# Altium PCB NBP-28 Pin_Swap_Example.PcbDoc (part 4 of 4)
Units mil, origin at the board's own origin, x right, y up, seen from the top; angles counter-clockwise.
Board outline 2716.54 x 4967.15 mil, 10 copper layers (Top Layer, Mid-Layer 1, VCC1V2, Mid-Layer 2, VCC, GND, MidLayer4, VCCINT, Mid-Layer 3, Bottom Layer), stack 81 mil thick; 254 components, 445 nets, 1667 pads, 770 vias.
Unrouted connection lines stored in the file: 611.
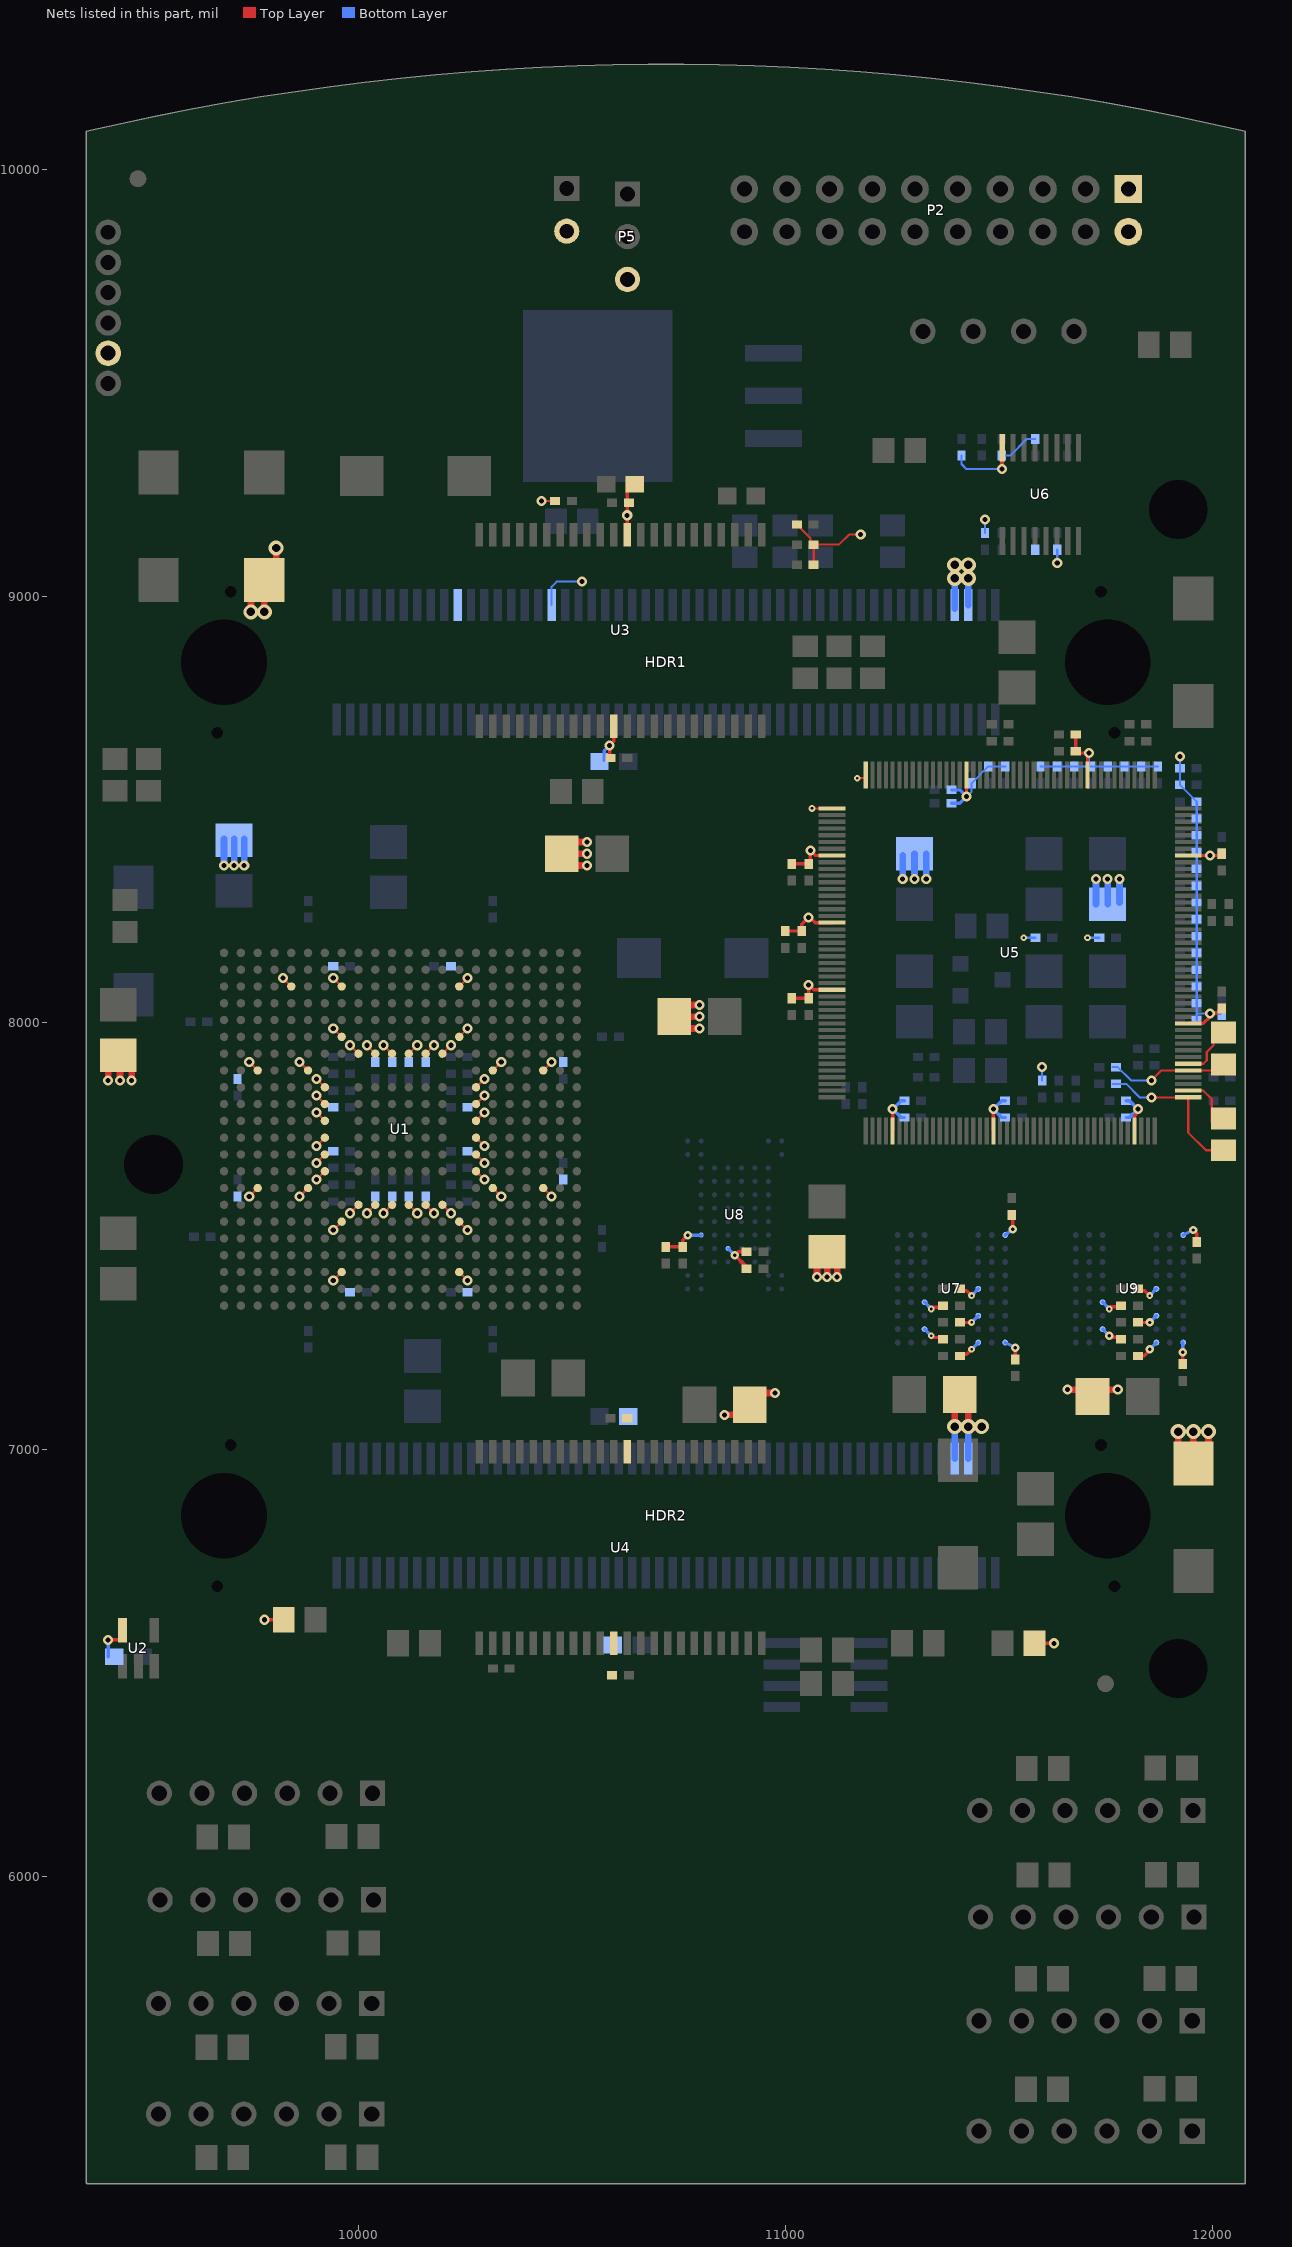
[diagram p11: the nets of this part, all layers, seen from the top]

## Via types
v1: diameter 23.62, hole 11.81, Top Layer to Bottom Layer, 495 vias
v2: diameter 78.74, hole 47.24, Top Layer to Bottom Layer, 101 vias
v3: diameter 15.75, hole 5.91, Top Layer to Bottom Layer, 92 vias
v4: diameter 35.43, hole 19.68, Top Layer to Bottom Layer, 59 vias
v5: diameter 19.68, hole 7.87, Top Layer to Bottom Layer, 23 vias

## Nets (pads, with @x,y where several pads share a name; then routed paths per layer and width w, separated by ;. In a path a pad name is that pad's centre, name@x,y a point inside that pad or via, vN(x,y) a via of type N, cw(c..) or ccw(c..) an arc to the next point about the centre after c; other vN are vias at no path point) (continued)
VCC3V3: C1.2 C12.1 C13.1 C14.1 C15.1 C30.1 C31.1 C32.1 C33.1 C34.1 C35.1 C36.1 C37.1 C38.1 C39.1 C40.1 C41.1 C42.1 C43.1 C44.1 C45.1 C46.1 C47.1 C48.1 C49.1 C50.1 C51.1 C52.1 C53.1 C54.1 C55.1 C56.1 C57.1 C58.1 C62.1 C66.1 C67.1 C68.1 C69.1 C70.1 C71.1 C72.1 C73.1 C74.1 C75.1 C76.1 C77.1 C78.1 C79.1 C80.1 C81.1 C82.1 C83.1 C84.1 C85.1 C86.1 C87.1 C102.1 C103.1 C104.1 C105.1 C106.1 C107.1 C108.1 C109.1 C110.1 C111.1 C112.1 C113.1 C114.1 C115.1 C116.1 C117.1 C118.1 C119.1 C120.1 C121.1 C122.1 C126.1 C127.1 HDR1.34 HDR1.94 HDR1.96 HDR2.94 HDR2.96 P1.2 P2.1 P2.2 P5.3 R1.1 R5.1 R15.2 R16.2 R17.2 R18.2 R20.2 R21.2 R22.2 R23.2 R24.2 R25.2 R26.2 R27.2 R28.2 R29.2 R30.2 R31.2 R32.2 R33.2 R34.2 R35.2 R39.2 R40.2 R41.2 R42.2 R43.2 R45.2 R48.2 R49.2 R50.2 R51.2 R52.2 R53.2 R54.2 R55.2 R56.2 R57.2 R61.1 R62.1 R67.1 TP1.1 U1.C8 U1.C15 U1.F8 U1.F15 U1.G9 U1.G10 U1.G11 U1.G12 U1.G13 U1.G14 U1.H3 U1.H6 U1.H17 U1.H20 U1.J7 U1.J16 U1.K7 U1.K16 U1.L7 U1.L16 U1.M7 U1.M16 U1.N7 U1.N16 U1.P7 U1.P16 U1.R3 U1.R6 U1.R17 U1.R20 U1.T9 U1.T10 U1.T11 U1.T12 U1.T13 U1.T14 U1.U8 U1.U15 U1.Y8 U1.Y15 U2.5 U3.11 U3.33 U4.11 U4.33 U5.1 U5.8 U5.18 U5.28 U5.49 U5.64 U5.85 U5.100 U5.125 U5.143 U5.161 U5.176 U6.16 U7.A7 U7.A9 U7.B3 U7.C7 U7.D3 U7.E7 U7.J9 U8.H7 U8.J5 U9.A7 U9.A9 U9.B3 U9.C7 U9.D3 U9.E7 U9.J9 | length 8194.9
  Top Layer w5: v1(9743.57,7593.48) U1.R3@9763.26,7613.17 ; v1(9743.57,7908.45) U1.H3@9763.26,7888.76 ; v1(9861.68,7593.48) U1.R6@9881.37,7613.17 ; v1(9861.68,7908.45) U1.H6@9881.37,7888.76 ; v1(9901.05,7632.85) U1.P7@9920.74,7652.54 ; v1(9901.05,7672.22) U1.N7@9920.74,7691.91 ; v1(9901.05,7711.59) U1.M7@9920.74,7731.28 ; v1(9901.05,7790.34) U1.L7@9920.74,7770.65 ; v1(9901.05,7829.71) U1.K7@9920.74,7810.02 ; v1(9901.05,7869.08) U1.J7@9920.74,7849.39 ; v1(9940.42,7396.63) U1.Y8@9960.11,7416.32 ; v1(9940.42,7514.74) U1.U8@9960.11,7534.43 ; v1(9940.42,7987.19) U1.F8@9960.11,7967.5 ; v1(9940.42,8105.3) U1.C8@9960.11,8085.61 ; v1(9979.79,7554.11) U1.T9@9999.48,7573.8 ; v1(9979.79,7947.82) U1.G9@9999.48,7928.13 ; v1(10019.16,7554.11) U1.T10@10038.85,7573.8 ; v1(10019.16,7947.82) U1.G10@10038.85,7928.13 ; v1(10058.53,7554.11) U1.T11@10078.22,7573.8 ; v1(10058.53,7947.82) U1.G11@10078.22,7928.13 ; U1.T12@10117.59,7573.8 v1(10137.27,7554.11) ; U1.G12@10117.59,7928.13 v1(10137.27,7947.82) ; U1.T13@10156.96,7573.8 v1(10176.64,7554.11) ; U1.G13@10156.96,7928.13 v1(10176.64,7947.82) ; U1.T14@10196.33,7573.8 v1(10216.01,7554.11) ; U1.G14@10196.33,7928.13 v1(10216.01,7947.82) ; U1.Y15@10235.7,7416.32 v1(10255.38,7396.63) ; U1.U15@10235.7,7534.43 v1(10255.38,7514.74) ; U1.F15@10235.7,7967.5 v1(10255.38,7987.19) ; U1.C15@10235.7,8085.61 v1(10255.38,8105.3) ; U1.P16@10275.07,7652.54 v1(10294.75,7632.85) ; U1.N16@10275.07,7691.91 v1(10294.75,7672.22) ; U1.M16@10275.07,7731.28 v1(10294.75,7711.59) ; U1.L16@10275.07,7770.65 v1(10294.75,7790.34) ; U1.K16@10275.07,7810.02 v1(10294.75,7829.71) ; U1.J16@10275.07,7849.39 v1(10294.75,7869.08) ; U1.R17@10314.44,7613.17 v1(10334.12,7593.48) ; U1.H17@10314.44,7888.76 v1(10334.12,7908.45) ; v1(10428.61,9223.41) R17.2@10460.11,9223.41 ; U1.R20@10432.55,7613.17 v1(10452.23,7593.48) ; U1.H20@10432.55,7888.76 v1(10452.23,7908.45) ; R24.2@11027.04,9168.29 11058.53,9136.79 R15.2@11058.53,9121.04 ; v3(11062.47,8502.93) U5.1@11109.71,8502.93 ; R18.2@11066.41,9073.8 R15.2@11066.41,9121.04 11125.46,9121.04 11149.08,9144.67 v1(11176.64,9144.67) ; v3(11168.77,8573.8) U5.176@11188.45,8573.8
  Top Layer w7.87: v1(9412.86,6554.11) U2.5@9452.23,6554.11 ; v1(9779,6601.36) R16.2@9824.28,6601.36 ; C53.1@10590.03,8621.04 10588.06,8623.01 v1(10588.06,8650.57) 10597.9,8660.41 U3.11@10597.9,8695.85 ; U3.33@10629.4,9139.74 U3.33@10629.4,9144.67 v1(10629.4,9189.94) C51.1@10629.4,9274.59 ; C105.1@10719.95,7475.37 C104.1@10759.32,7475.37 10759.32,7491.12 v5(10771.13,7502.93) ; C103.1@10908.93,7424.19 10908.93,7428.13 v5(10881.37,7455.69) 10889.24,7463.56 C106.1@10908.93,7463.56 ; C71.1@10999.48,8215.53 C81.1@11038.85,8215.53 11038.85,8231.28 v1(11054.59,8247.03) 11058.53,8247.03 11070.34,8235.22 U5.18@11109.71,8235.22 ; C70.1@11015.22,8058.05 C80.1@11054.59,8058.05 v1(11054.59,8089.55) 11066.41,8077.74 U5.28@11109.71,8077.74 ; C68.1@11015.22,8373.01 C78.1@11054.59,8373.01 ; C78.1@11058.53,8376.95 v1(11058.53,8404.51) 11070.34,8392.7 U5.8@11109.71,8392.7 ; U5.49@11251.45,7747.03 v1(11251.45,7798.21) ; v3(11342,7266.71) 11345.93,7262.78 C119.1@11373.49,7262.78 ; v3(11342,7329.7) 11345.93,7333.64 C121.1@11365.62,7333.64 ; C120.1@11404.99,7223.41 11424.67,7223.41 v3(11436.48,7235.22) ; C109.1@11404.99,7373.01 11424.67,7373.01 v3(11436.48,7361.2) ; C118.1@11408.93,7298.21 v3(11436.48,7298.21) ; v1(11424.67,8530.49) U5.161@11424.67,8581.67 ; U5.64@11487.67,7747.03 v1(11487.67,7798.21) ; v1(11507.35,9298.21) U6.16@11507.35,9347.42 ; v5(11532.94,7516.71) C122.1@11532.94,7548.21 ; C108.1@11538.85,7215.53 v5(11538.85,7239.15) ; R5.1@11584.12,6546.24 v1(11629.4,6546.24) ; C86.1@11680.58,8636.79 C76.1@11680.58,8676.16 ; C86.1@11684.52,8632.85 v1(11712.08,8632.85) ; U5.143@11708.14,8581.67 v1@11708.14,8628.92 ; v3@11758.32,7330.7 11762.26,7334.64 C116.1@11781.95,7334.64 ; v5@11758.33,7267.71 11762.26,7263.78 C115.1@11789.82,7263.78 ; U5.85@11818.37,7747.03 11818.37,7782.46 11826.25,7790.33 v1(11826.25,7798.21) ; C117.1@11821.32,7220.47 11841,7220.47 v5@11852.82,7232.28 ; C107.1@11822.31,7373.01 11842,7373.01 v3(11853.81,7361.2) ; C112.1@11826.25,7298.21 v5(11853.81,7298.21) ; C114.1@11931.56,7200.78 v5(11931.56,7228.34) ; U5.100@11944.36,7999 11979.79,7999 11995.54,8014.74 v1(11995.54,8022.62) 12011.29,8022.62 C84.1@12023.1,8034.43 ; U5.125@11944.36,8392.7 v1(11995.54,8392.7) C75.1@12019.16,8392.7 ; v5(11956.17,7514.74) 11964.04,7506.87 C113.1@11964.04,7487.18
  Top Layer w15.75: C32.1@9404.99,7928.13 9412.86,7924.19 v1(9412.86,7865.14) ; C32.1@9436.48,7928.13 9440.42,7924.19 v1(9440.42,7865.14) ; v1(9467.98,7865.14) C32.1@9467.98,7928.13 ; v4(9747.51,8963.56) C127.1@9747.51,9026.55 ; v4(9779,8963.56) C127.1@9779,9022.62 ; C127.1@9806.56,9050.18 v4(9806.56,9113.17) ; C49.1@10471.92,8369.07 v1(10534.91,8369.07) ; C49.1@10471.92,8424.19 v1(10534.91,8424.19) ; C49.1@10475.85,8396.63 v1(10534.91,8396.63) ; C31.1@10735.7,7987.18 v1(10798.69,7987.18) ; C31.1@10735.7,8042.3 v1(10798.69,8042.3) ; C31.1@10739.63,8014.74 v1(10798.69,8014.74) ; v1(10857.74,7081.67) C50.1@10908.93,7081.67 ; C50.1@10912.86,7132.85 v1(10975.85,7132.85) ; v1(11074.28,7404.51) C102.1@11074.28,7447.81 ; v1(11097.9,7404.51) C102.1@11097.9,7455.69 ; v1(11121.52,7404.51) C102.1@11121.52,7451.75 ; v4(11397.11,7054.11) C110.1@11397.11,7113.17 ; C110.1@11408.93,7128.92 11428.61,7109.23 v4(11428.61,7054.11) ; v1(11660.89,7140.73) v1(11779,7140.73) ; C126.1@11920.74,6999 v4(11920.74,7042.3) ; C126.1@11956.17,6967.5 v4(11956.17,7042.3) ; C126.1@11991.6,6983.25 v4(11991.6,7042.3)
  Bottom Layer w5: HDR1.34@10452.23,8979.31 10452.23,9022.62 10464.04,9034.43 v1(10523.1,9034.43) ; R67.1@11412.86,9329.7 11412.86,9310.02 11424.67,9298.21 v1(11507.35,9298.21) ; v1(11424.67,8530.49) 11436.48,8542.3 R56.2@11436.48,8561.99 R55.2@11475.85,8601.36 R54.2@11515.22,8601.36 ; R57.2@11467.98,9148.6 v1(11467.98,9180.1) ; C62.1@11507.35,9329.7 11527.04,9329.7 11566.41,9369.07 R62.1@11586.09,9369.07 ; v3(11558.53,8199.78) R29.2@11586.09,8199.78 ; R52.2@11597.9,8601.36 R51.2@11712.08,8601.36 ; R20.2@11601.84,7865.14 v1(11601.84,7896.63) ; v1(11637.27,9077.74) R61.1@11637.27,9109.23 ; v3(11708.14,8199.78) R30.2@11735.7,8199.78 ; v1(11712.08,8632.85) R51.2@11712.08,8601.36 ; R41.2@11873.49,8601.36 R42.2@11834.12,8601.36 R51.2@11712.08,8601.36 ; v1(11924.67,8624.98) R49.2@11924.67,8597.42 R40.2@11924.67,8558.05 R48.2@11964.04,8518.68 R39.2@11964.04,8479.31 R28.2@11964.04,8321.83 R35.2@11964.04,8203.72 R21.2@11964.04,8085.61 11964.04,8022.62 ; R23.2@11964.04,8006.87 11964.04,8022.62 ; R26.2@11967.98,8392.7 v1(11995.54,8392.7) ; v1(11995.54,8022.62) 11964.04,8022.62
  Bottom Layer w7.87: C1.2@9412.86,6514.74 v1(9412.86,6554.11) ; C52.1@10575.26,8615.14 10575.26,8637.78 v1(10588.06,8650.57) ; v5(10771.13,7502.93) U8.H7@10802.63,7502.93 ; U8.J5@10865.62,7471.44 v5(10881.37,7455.69) ; C79.1@11279,7778.52 11271.13,7778.52 v1(11251.45,7798.21) 11271.13,7817.89 C69.1@11279,7817.89 ; U7.B3@11326.25,7282.46 v3(11342,7266.71) ; U7.D3@11326.25,7345.45 v3(11342,7329.7) ; C87.1@11389.24,8514.74 11408.93,8514.74 v1(11424.67,8530.49) 11408.93,8546.24 C77.1@11389.24,8546.24 ; v3(11436.48,7235.22) U7.A7@11452.23,7250.96 ; v3(11436.48,7298.21) U7.C7@11452.23,7313.96 ; v3(11436.48,7361.2) U7.E7@11452.23,7376.95 ; v1(11507.35,9298.21) C62.1@11507.35,9329.7 ; U7.A9@11515.22,7250.96 v5(11538.85,7239.15) ; U7.J9@11515.22,7502.93 v5(11532.94,7516.71) ; C83.1@11515.22,7778.52 11507.35,7778.52 v1(11487.67,7798.21) 11507.35,7817.89 C73.1@11515.22,7817.89 ; U9.B3@11743.57,7282.46 v5(11759.32,7266.71) ; U9.D3@11743.57,7345.45 v3(11759.32,7329.7) ; C82.1@11798.69,7778.52 11806.56,7778.52 v1(11826.25,7798.21) 11806.56,7817.89 C72.1@11798.69,7817.89 ; v5(11853.81,7235.22) U9.A7@11869.56,7250.96 ; v5(11853.81,7298.21) U9.C7@11869.56,7313.96 ; v3(11853.81,7361.2) U9.E7@11869.56,7376.95 ; v5(11931.56,7228.34) U9.A9@11931.56,7251.96 ; U9.J9@11932.55,7502.93 v5(11956.17,7514.74) ; v1(11995.54,8022.62) C74.1@12019.16,8022.62 ; v1(11995.54,8392.7) C85.1@12019.16,8392.7
  Bottom Layer w15.75: v1(9684.52,8369.07) C30.1@9684.52,8432.07 ; v1(9708.14,8369.07) C30.1@9708.14,8428.13 C30.1@9708.14,8432.07 ; v1(9731.76,8369.07) C30.1@9731.76,8432.07 ; v1(11275.07,8337.58) C67.1@11275.07,8392.7 ; v1(11302.63,8337.58) C67.1@11302.63,8396.63 ; v1(11330.19,8337.58) C67.1@11330.19,8396.63 ; HDR2.94@11397.12,6979.31 v4(11397.11,7054.11) v4(11428.61,7054.11) ; HDR1.94@11397.11,8971.44 HDR1.94@11397.11,8979.31 v4(11397.11,9042.3) ; HDR2.96@11428.61,6979.31 v4(11428.61,7054.11) ; HDR1.96@11428.61,8979.31 v4(11428.61,9042.3) ; v4(11460.11,7054.11) v4(11428.61,7054.11) ; C66.1@11727.82,8278.52 v1(11727.82,8337.58) ; C66.1@11755.38,8278.52 v1(11755.38,8337.58) ; C66.1@11782.94,8282.46 v1(11782.94,8337.58) ; v4(11397.11,9042.3) v4(11428.61,9042.3) ; v4(11397.11,9042.3) v4(11397.11,9073.8) v4(11428.61,9073.8) v4(11428.61,9042.3)
VDRIVE: HDR1.20 U1.C5 | length 27.8
  Top Layer w5: v1(9822.31,8105.3) U1.C5@9842,8085.61
XTALIN: C59.2 R38.1 U5.93 | length 278.7
  Top Layer w5: v1(11857.74,7865.14) 11881.37,7888.76 U5.93@11944.36,7888.76 R38.1@12023.1,7888.76
  Bottom Layer w5: C59.2@11767.19,7896.63 C59.2@11775.07,7896.63 11779,7896.63 11810.5,7865.14 v1(11857.74,7865.14)
XTALIN_32K: C60.2 R47.1 U5.89 | length 372.7
  Top Layer w5: v1(11857.74,7825.77) U5.89@11944.36,7825.77 11944.36,7743.09 11985.7,7701.75 R47.1@12027.04,7701.75
  Bottom Layer w5: C60.2@11767.19,7857.26 C60.2@11775.07,7857.26 11798.69,7857.26 11830.19,7825.77 v1(11857.74,7825.77)
XTALOUT: R38.2 U5.94 | length 108.2
  Top Layer w5: U5.94@11944.36,7904.51 11979.79,7904.51 11987.67,7912.38 11987.67,7932.07 12003.41,7947.81 R38.2@12003.41,7967.5
XTALOUT_32K: R47.2 U5.90 | length 118.4
  Top Layer w5: U5.90@11944.36,7841.52 11979.79,7841.52 11999.48,7821.83 R47.2@11999.48,7766.71
pads on no net: D1.2 HDR1.91 HDR1.MH1 HDR1.MH2 HDR1.MH3 HDR1.MH4 HDR1.MH5 HDR1.MH6 HDR2.MH1 HDR2.MH2 HDR2.MH3 HDR2.MH4 HDR2.MH5 HDR2.MH6 P3_ch1.3 P3_ch1.6 P3_ch2.3 P3_ch2.6 P3_ch3.3 P3_ch3.6 P3_ch4.3 P3_ch4.6 P4_ch1.3 P4_ch1.6 P4_ch2.3 P4_ch2.6 P4_ch3.3 P4_ch3.6 P4_ch4.3 P4_ch4.6 U2.1 U5.145 U5.157 U5.162 U7.E2 U8.A1 U8.A2 U8.A7 U8.A8 U8.B1 U8.B7 U8.B8 U8.L1 U8.L2 U8.L7 U8.L8 U8.M1 U8.M2 U8.M7 U8.M8 U9.E2 U10.5 U10.8

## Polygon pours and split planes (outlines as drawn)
VCC1V2 on VCC1V2 (split plane): 10788.26,10226.6 10856.59,10225.42 10924.91,10223.45 10993.19,10220.69 11061.44,10217.14 11129.64,10212.8 11197.79,10207.67 11265.88,10201.76 11333.89,10195.06 11401.82,10187.58 11469.66,10179.31 11537.4,10170.26 11605.02,10160.43 11672.54,10149.81 11739.92,10138.42 11807.17,10126.25 11874.27,10113.31 11941.22,10099.59 12008.01,10085.09 12058.12,10073.61 12058.12,5299.8 9381.78,5299.8 9381.78,10073.63 9431.84,10085.09 9498.62,10099.59 9565.57,10113.31 9632.68,10126.25 9699.92,10138.42 9767.31,10149.81 9834.82,10160.43 9902.45,10170.26 9970.19,10179.31 10038.03,10187.58 10105.96,10195.06 10173.97,10201.76 10242.06,10207.67 10310.2,10212.8 10378.41,10217.14 10446.66,10220.69 10514.94,10223.45 10583.25,10225.42 10651.58,10226.6 10719.92,10227
VCC1V8 on VCC1V2 (split plane): 12044.9,8692.89 12044.9,7865 12044.9,6557.11 12039.13,6551.34 11375.87,6551.34 11305.1,6622.11 11305.1,7630 11304.71,7631.95 11303.6,7633.6 11100.1,7837.11 11100.1,8442.89 11353.6,8696.4 11353.61,8696.4 11382.11,8724.9 12012.89,8724.9
VCC3V3 on VCC (split plane): 10788.26,10226.6 10856.59,10225.42 10924.91,10223.45 10993.19,10220.69 11061.44,10217.14 11129.64,10212.8 11197.79,10207.67 11265.88,10201.76 11333.89,10195.06 11401.82,10187.58 11469.66,10179.31 11537.4,10170.26 11605.02,10160.43 11672.54,10149.81 11739.92,10138.42 11807.17,10126.25 11874.27,10113.31 11941.22,10099.59 12008.01,10085.09 12058.12,10073.61 12058.12,5299.8 9381.78,5299.8 9381.78,10073.63 9431.84,10085.09 9498.62,10099.59 9565.57,10113.31 9632.68,10126.25 9699.92,10138.42 9767.31,10149.81 9834.82,10160.43 9902.45,10170.26 9970.19,10179.31 10038.03,10187.58 10105.96,10195.06 10173.97,10201.76 10242.06,10207.67 10310.2,10212.8 10378.41,10217.14 10446.66,10220.69 10514.94,10223.45 10583.25,10225.42 10651.58,10226.6 10719.92,10227
GND on GND (split plane): 10788.26,10226.6 10856.59,10225.42 10924.91,10223.45 10993.19,10220.69 11061.44,10217.14 11129.64,10212.8 11197.79,10207.67 11265.88,10201.76 11333.89,10195.06 11401.82,10187.58 11469.66,10179.31 11537.4,10170.26 11605.02,10160.43 11672.54,10149.81 11739.92,10138.42 11807.17,10126.25 11874.27,10113.31 11941.22,10099.59 12008.01,10085.09 12058.12,10073.61 12058.12,5299.8 9381.78,5299.8 9381.78,10073.63 9431.84,10085.09 9498.62,10099.59 9565.57,10113.31 9632.68,10126.25 9699.92,10138.42 9767.31,10149.81 9834.82,10160.43 9902.45,10170.26 9970.19,10179.31 10038.03,10187.58 10105.96,10195.06 10173.97,10201.76 10242.06,10207.67 10310.2,10212.8 10378.41,10217.14 10446.66,10220.69 10514.94,10223.45 10583.25,10225.42 10651.58,10226.6 10719.92,10227
VCC2V5 on VCCINT (split plane): 10788.26,10226.6 10856.59,10225.42 10924.91,10223.45 10993.19,10220.69 11061.44,10217.14 11129.64,10212.8 11197.79,10207.67 11265.88,10201.76 11333.89,10195.06 11401.82,10187.58 11469.66,10179.31 11537.4,10170.26 11605.02,10160.43 11672.54,10149.81 11739.92,10138.42 11807.17,10126.25 11874.27,10113.31 11941.22,10099.59 12008.01,10085.09 12058.12,10073.61 12058.12,9459.09 12053.6,9463.6 12051.95,9464.71 12050,9465.1 11085,9465.1 11083.05,9464.71 11081.4,9463.6 10946.4,9328.6 10945.29,9326.95 10944.9,9325 10944.9,6615 10945.29,6613.05 10946.4,6611.4 11031.4,6526.4 11033.05,6525.29 11035,6524.9 12050,6524.9 12051.95,6525.29 12053.6,6526.4 12058.12,6530.91 12058.12,5299.8 9381.78,5299.8 9381.78,10073.63 9431.84,10085.09 9498.62,10099.59 9565.57,10113.31 9632.68,10126.25 9699.92,10138.42 9767.31,10149.81 9834.82,10160.43 9902.45,10170.26 9970.19,10179.31 10038.03,10187.58 10105.96,10195.06 10173.97,10201.76 10242.06,10207.67 10310.2,10212.8 10378.41,10217.14 10446.66,10220.69 10514.94,10223.45 10583.25,10225.42 10651.58,10226.6 10719.92,10227
+5V on VCCINT (split plane): 12054.9,9447.89 12054.9,6542.11 12047.89,6535.1 11037.11,6535.1 10955.1,6617.11 10955.1,9322.89 11087.11,9454.9 12047.89,9454.9

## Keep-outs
Top Layer:
  circle w10: c11750.4,6451.11 r98.43
  circle w10: c9482.69,9978.67 r98.43
Bottom Layer:
  circle w10: c11750.4,6451.11 r98.43
  circle w10: c9482.69,9978.67 r98.43
  rectangle: 11471.92,9707.66 11668.77,9802.14
Keep-Out Layer:
  the board outline again, w31.5

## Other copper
Bottom Layer:
  region: 11562.47,7439.94 11617.59,7439.94
VCCINT (plane layer: these items are gaps in the copper):
  lines w10: 10950,6615 11035,6530 11160,6530 12050,6530 12060,6540 12060,9450 12050,9460 11085,9460 10950,9325 10950,6615
VCC1V2 (plane layer: these items are gaps in the copper):
  lines w10: 11095,7835 11300,7630 11300,6620 11373.76,6546.24 11481.24,6546.24 12041.24,6546.24 12050,6555 12050,7865 12050,8695 12015,8730 11750,8730 11380,8730 11350,8700 11095,8445 11095,7835

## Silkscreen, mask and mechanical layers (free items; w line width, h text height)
Top Overlay:
  circle w5: c11920.74,9203.72 r98.43
  circle w5: c9519.16,7668.29 r98.43
  circle w5: c11920.74,6487.18 r62.99
  circle w5: c9519.16,7668.29 r62.99
  circle w5: c9519.16,7668.29 r108.27
  circle w5: c11920.74,9203.72 r62.99
  circle w5: c11920.74,9203.72 r108.27
  circle w10: c11605.78,7569.86 r106.3
  circle w10: c11578.22,7231.28 r106.3
  circle w10: c10452.23,9282.46 r98.43
  lines w3.15: 11086.09,9589.55 11290.82,9589.55 11322.31,9621.04 ; 11093.97,9660.41 11401.05,9660.41 11440.42,9621.04 ; 11440.42,9660.41 11519.16,9660.41 11558.53,9621.04 ; 11676.64,9621.04 11716.01,9660.41 11822.31,9660.41 ; 12034.91,8010.81 12050.66,8026.55 12050.66,8199.78
  lines w5: 9361.68,6378.92 9401.05,6378.92 9404.68,6378.23 9408.01,6376.03 9410.2,6372.7 9410.89,6369.08 9410.89,6329.7 ; 9361.68,6388.76 9420.74,6388.76 9420.74,6329.7 ; 9361.68,7820.85 9440.42,7820.85 9444.05,7821.54 9447.38,7823.73 9449.57,7827.06 9450.26,7830.69 9450.26,7860.22 9449.57,7863.84 9447.38,7867.18 9444.05,7869.37 9440.42,7870.06 9361.68,7870.06 ; 9361.68,9302.15 9420.74,9302.15 9420.74,9357.26 ; 9361.68,9321.83 9401.05,9321.83 9404.68,9322.52 9408.01,9324.71 9410.2,9328.05 9410.89,9331.67 9410.89,9355.3 ; 9361.73,9345.45 cw(c10719.97,3565.9) 12078.22,9345.45 ; 9361.73,9424.19 cw(c10719.97,3644.64) 12078.22,9424.19 ; 9362.02,7189.51 9452.57,7189.51 9452.57,7264.31 9362.05,7264.31 ; 9362.02,8421.79 9452.57,8421.79 9452.57,8496.59 9362.05,8496.59 ; 9479.79,7668.29 9519.16,7668.29 ; 9519.16,7628.92 9519.16,7668.29 ; 9519.16,7707.66 9519.16,7668.29 ; 9558.53,7668.29 9519.16,7668.29 ; 9979.79,9455.69 9979.79,9404.51 10030.97,9404.51 10030.97,9459.63 ; 10085.11,9466.52 10085.11,9410.81 10085.8,9407.18 10087.99,9403.85 10091.33,9401.66 10094.95,9400.96 10124.48,9400.96 10128.1,9401.66 10131.44,9403.85 10133.63,9407.18 10134.32,9410.81 10134.32,9472.42 ; 10090.03,6546.24 10129.4,6546.24 ; 10129.4,6506.87 10129.4,6546.24 ; 10129.4,6585.61 10129.4,6546.24 ; 10168.77,6546.24 10129.4,6546.24 ; 11271.13,6546.24 11310.5,6546.24 ; 11305.58,9472.42 11305.58,9410.81 11306.27,9407.18 11308.46,9403.85 11311.8,9401.66 11315.42,9400.96 11344.95,9400.96 11348.57,9401.66 11351.91,9403.85 11354.1,9407.18 11354.79,9410.81 11354.79,9466.52 ; 11310.5,6506.87 11310.5,6546.24 ; 11310.5,6585.61 11310.5,6546.24 ; 11318.37,9471.44 11318.37,9428.13 11369.55,9428.13 11369.56,9467.5 ; 11349.87,6546.24 11310.5,6546.24 ; 11819,6524.21 cw(c11920.74,6487.18) 11844.18,6410.63 ; 11828.25,6520.85 cw(c11920.74,6487.19) 11845.34,6423.92 ; 11881.37,6487.18 11920.74,6487.18 ; 11881.37,9203.72 11920.74,9203.72 ; 11920.74,6447.81 11920.74,6487.18 ; 11920.74,6526.55 11920.74,6487.18 ; 11920.74,9164.35 11920.74,9203.72 ; 11920.74,9243.09 11920.74,9203.72 ; 11960.11,6487.18 11920.74,6487.18 ; 11960.11,9203.72 11920.74,9203.72 ; 12019.16,6329.7 12019.16,6388.76 12078.22,6388.76 ; 12019.16,9357.26 12019.16,9302.14 12078.22,9302.14 ; 12029,6329.7 12029,6369.08 12029.7,6372.7 12031.89,6376.03 12035.22,6378.23 12038.85,6378.92 12078.22,6378.92 ; 12029,9355.3 12029,9331.67 12029.7,9328.05 12031.89,9324.71 12035.22,9322.52 12038.85,9321.83 12078.22,9321.83 ; 12078.19,7191.91 11987.66,7191.91 11987.66,7266.71 12078.22,7266.71 ; 12078.22,7820.85 11999.48,7820.85 11995.85,7821.54 11992.52,7823.73 11990.33,7827.06 11989.63,7830.69 11989.63,7860.22 11990.33,7863.84 11992.52,7867.18 11995.85,7869.37 11999.48,7870.06 12078.22,7870.06 ; 12078.53,8424.19 11988.01,8424.19 11988.01,8499 12078.56,8499 ; 10090.03,6506.87 cw(c10090.03,6546.24) 10090.03,6585.61 10168.77,6585.61 cw(c10168.77,6546.24) 10168.77,6506.87 10090.03,6506.87 ; 11271.13,6506.87 cw(c11271.13,6546.24) 11271.13,6585.61 11349.87,6585.61 cw(c11349.87,6546.24) 11349.87,6506.87 11271.13,6506.87
  text "LH79520 EXT DEBUG" at 11082.15,10109.23 h31.5
  text "OPEN: INTEGRATED" at 10629.4,9648.6 h31.5 r90
  text "CLOSED: EXTERNAL" at 10672.7,9648.6 h31.5 r90
  text "LH79520 DEBUG SELECT" at 10582.15,9593.48 h31.5 r90
  text "EXT DEBUG" at 11771.13,9499 h31.5
  text "ALL" at 10412.86,9310.02 h31.5
  text "4k7" at 10408.93,9262.78 h31.5
  text "ALL" at 11566.41,7585.61 h31.5
  text "100nF" at 11558.53,7538.37 h31.5
  text "ALL" at 11554.59,7243.09 h31.5
  text "10nF" at 11562.47,7195.85 h31.5
  text "LOADED" at 10042.78,6396.63 h31.5
  text "POWER" at 11251.45,6396.63 h31.5
  text "Altium Advanced Training: '.Pcb_File_Name_No_Path'" at 9380,5166.66 h50
Bottom Overlay:
  drawing of 888 lines, arcs and shapes, not listed
  text "NBP#28" at 11738.59,10045.6 h31.5
  text "REV 1.00" at 11407.89,10041.66 h31.5
  text "1" at 9911.68,8629.7 h31.5
  text "1" at 9903.95,6675.52 h31.5
Mechanical 1:
  lines w9.84: 9361.67,5229.55 9361.7,10089.55 cw(c10719.95,4310) 12078.22,10089.54 12078.22,5229.55 ; 9361.68,5229.7 12078.22,5229.7
  text "PCB boundary coincides with centre-line of tracks and arc" at 9356.76,4813.24 h31.5
Mechanical 2:
  text ".Printout_Name" at 9356.76,5049.46 h31.5
Mechanical 3:
  text ".Printout_Name" at 9356.76,4891.98 h31.5
Mechanical 11:
  drawing of 689 lines, arcs and shapes, not listed
  text "NBP28 Rev1.00" at 20080.76,14835.7 h50
  text "DESIGN INFORMATION" at 17875.76,14830.7 h60
  text "BOARD NAME:" at 19355.76,14830.7 h60
  text "BOARD TECHNOLOGY" at 17875.76,14730.7 h60
  text "BOARD SIZE (REFER ALSO PROFILING INFORMATION)" at 19775.76,14730.7 h50
  text "5.000" at 17959.26,14644.52 h60
  text "69.00mm" at 19882.84,14641.18 h60
  text "12.000" at 18495.39,14638.57 h60
  text "81.00mm" at 20788.36,14637.24 h60
  text "5.000" at 19047.77,14632.71 h60
  text "X" at 20510.76,14610.7 h70
  text "(MIN. TRACK/   PADS  /   CLEARANCE     IN 0.001'')" at 17815.76,14530.7 h50
  text "MINIMUM ANNULAR RING 0.125MM (0.005'') EXTERNAL PER IPC-2221 CLASS 3 LEVEL C AND IS THE" at 17875.76,14430.7 h50
  text "MANUFACTURING REGISTRATION ALLOWANCE" at 17875.76,14340.7 h50
  text "LAND SIZE CALCULATION MINIMUM - NOMINAL HOLE SIZE + 0.508MM (0.020'')" at 17875.76,14230.7 h50
  text "CIRCUIT TYPE:" at 17875.76,14050.7 h60
  text "SS" at 18775.76,14050.7 h50
  text "DS" at 19475.76,14050.7 h50
  text "X" at 20050.76,14050.7 h60
  text "PTH" at 20175.76,14050.7 h50
  text "ML" at 20605.76,14050.7 h50
  text "X" at 20755.76,14050.7 h60
  text "No. OF" at 20875.76,14050.7 h50
  text "8" at 21559.26,14044.52 h60
  text "FINGER CONNECTOR DIM PER:" at 17875.76,13930.7 h60
  text "AS SHOWN" at 20875.76,13930.7 h50
  text "No. OFF TOTAL" at 18535.76,13820.7 h60
  text "ONE SIDE" at 20175.76,13820.7 h50
  text "BOTH SIDES" at 20875.76,13810.7 h50
  text "VIAS:" at 17875.76,13705.7 h60
  text "NONE" at 18325.76,13705.7 h45
  text "X" at 18655.76,13705.7 h60
  text "FEED THRU'" at 18775.76,13705.7 h45
  text "TENTED" at 19475.76,13705.7 h45
  text "BURIED LAYER SEQUENCE" at 20175.76,13705.7 h45
  text "UNIQUE DRILL" at 18775.76,13585.7 h45
  text "2 SIZE" at 19475.76,13585.7 h45
  text "BLIND LAYER SEQUENCE" at 20175.76,13585.7 h45
  text "Layer Stack Manager (Protel)" at 19270.76,13495.7 h50
  text "X" at 20755.76,13495.7 h60
  text "AS SHOWN" at 20875.76,13495.7 h50
  text "LAYER CONSTRUCTION PER:" at 17875.76,13490.7 h60
  text "Protel" at 21065.76,13390.7 h50
  text "(PFW)" at 21470.76,13385.7 h50
  text "ARTWORK:" at 17875.76,13380.7 h60
  text "MANUAL" at 18775.76,13380.7 h50
  text "DIGITISED" at 19475.76,13380.7 h50
  text "X" at 20055.76,13380.7 h60
  text "CAD" at 20175.76,13380.7 h50
  text "TYPE" at 20605.76,13380.7 h50
  text "ARTWORK/PATTERN MASTER LIST" at 17875.76,13195.7 h60
  text "DESCRIPTION" at 17925.76,13100.7 h50
  text "DRAWING No./CAD FILE REF." at 18660.76,13100.7 h50
  text "LAYER NAME" at 20285.76,13100.7 h50
  text "GERBER FILE REF" at 21102.77,13097.71 h50
  text "PCB FILE" at 17865.76,13000.7 h50
  text "NBP28 Rev1.00" at 18667.29,12998.46 h50
  text "PcbDoc" at 19897.77,12997.71 h40
  text "Top Paste Mask" at 20219.77,12900.7 h40
  text "GTP" at 21897.77,12897.71 h50
  text "GERBER FILE" at 17865.76,12895.7 h50
  text "GTO" at 21895.76,12799.72 h50
  text "Top Overlay" at 20219.77,12798.7 h40
  text "GERBER FILE" at 17865.76,12795.7 h50
  text "Top Solder Mask" at 20219.77,12702.71 h40
  text "GTS" at 21897.77,12697.71 h50
  text "GERBER FILE" at 17865.76,12695.7 h50
  text "TOP LAYER" at 20219.77,12600.7 h40
  text "GTL" at 21897.77,12597.71 h50
  text "GERBER FILE" at 17865.76,12595.7 h50
  text "MIDLAYER3" at 20219.8,12500.77 h40
  text "G3" at 21893.03,12500.77 h50
  text "GERBER FILE" at 17865.76,12495.7 h50
  text "MIDLAYER1" at 20219.8,12402.35 h40
  text "G1" at 21893.03,12402.35 h50
  text "GERBER FILE" at 17865.76,12395.7 h50
  text "VCC" at 20219.77,12300.7 h40
  text "GERBER FILE" at 17865.76,12295.7 h50
  text "GP2" at 21897.77,12291.41 h50
  text "GND" at 20219.8,12205.5 h40
  text "GP1" at 21893.03,12205.5 h50
  text "GERBER FILE" at 17865.76,12195.7 h50
  text "VCCINT" at 20219.8,12107.07 h40
  text "GERBER FILE" at 17865.76,12095.7 h50
  text "GP3" at 21897.77,12094.56 h50
  text "MIDLAYER2" at 20219.8,12008.65 h40
  text "GERBER FILE" at 17865.76,11995.7 h50
  text "G2" at 21897.77,11996.14 h50
  text "BOTTOM LAYER" at 20219.77,11900.7 h40
  text "GBL" at 21897.77,11897.71 h50
  text "GERBER FILE" at 17865.76,11895.7 h50
  text "Bottom Solder Mask" at 20219.77,11802.71 h40
  text "GBS" at 21897.77,11797.71 h50
  text "GERBER FILE" at 17865.76,11795.7 h50
  text "Bottom Overlay" at 20219.77,11700.7 h40
  text "GBO" at 21897.77,11697.71 h50
  text "GERBER FILE" at 17865.76,11695.7 h50
  text "Bottom Paste Mask" at 20219.77,11602.71 h40
  text "GBP" at 21897.77,11597.71 h50
  text "GERBER FILE" at 17865.76,11595.7 h50
  text "PCB Boundary" at 20219.77,11500.7 h40
  text "GM1" at 21897.77,11497.71 h50
  text "GERBER FILE" at 17865.76,11495.7 h50
  text "Dimensions" at 20219.77,11400.7 h40
  text "GM4" at 21897.77,11397.71 h50
  text "GERBER FILE" at 17865.76,11395.7 h50
  text "APERTURE LIST" at 17865.76,11300.7 h50
  text "APR" at 19937.14,11297.71 h50
  text "DRILL REPORT" at 17865.76,11200.7 h50
  text "DRR" at 19937.14,11197.71 h50
  text "DRILL FILE" at 17855.28,11098.07 h50
  text "DRL" at 19932.21,11092.4 h50
  text "TXT" at 19926.15,10997.67 h50
  text "EXCELLON DRILL" at 17852.33,10994.72 h50
  text "MATERIAL:" at 17875.76,10790.7 h60
  text "GLASS FIBRE EPOXY RESIN NEMA GRADE FR4 (MIL-S-13949H)" at 18885.76,10780.7 h50
  text "X" at 18780.76,10775.7 h60
  text "THICKNESS:" at 18185.76,10665.7 h50
  text "0.8mm" at 18885.76,10665.7 h50
  text "1.2mm" at 19580.76,10665.7 h50
  text "1.6mm" at 20275.76,10665.7 h50
  text "2.4mm" at 20975.76,10665.7 h50
  text "3.2mm" at 21675.76,10665.7 h50
  text "X" at 20180.76,10660.7 h60
  text "TOLERANCE:" at 18180.76,10545.7 h50
  text "IN A/W IPC-D-300G CLASS" at 18875.76,10545.7 h50
  text "3 LEVEL B" at 20250.76,10545.7 h50
  text "OTHER +/-" at 20975.76,10545.7 h50
  text "X" at 18780.76,10540.7 h60
  text "BOW & TWIST:" at 18085.76,10425.7 h50
  text "IN A/W IPC-D-300G CLASS" at 18875.76,10425.7 h50
  text "3 LEVEL B" at 20250.76,10425.7 h50
  text "AS SHOWN" at 20980.76,10420.7 h50
  text "X" at 18780.76,10415.7 h60
  text "COPPER THICKNESS (FINISHED)" at 18180.76,10295.7 h50
  text "OUTER:" at 18370.76,10205.7 h50
  text "18um" at 18885.76,10205.7 h50
  text "35um" at 19950.76,10205.7 h50
  text "70um" at 20985.76,10205.7 h50
  text "X" at 19842.77,10197.71 h60
  text "INNER SIGNAL:" at 18040.76,10085.7 h50
  text "18um" at 18885.76,10085.7 h50
  text "35um" at 19950.76,10085.7 h50
  text "70um" at 20985.76,10085.7 h50
  text "X" at 19840.76,10077.71 h60
  text "INNER PWR:" at 18185.76,9965.7 h50
  text "18um" at 18885.76,9965.7 h50
  text "35um" at 19950.76,9965.7 h50
  text "70um" at 20985.76,9965.7 h50
  text "X" at 19845.76,9960.7 h60
  text "STRUCTURE:" at 17875.76,9845.7 h60
  text "REFER" at 18885.76,9845.7 h50
  text "AS PER DRAWING No." at 18880.76,9720.7 h50
  text "AS SHOWN" at 20980.76,9720.7 h50
  text "X" at 20880.76,9715.7 h60
  text "DRILLING:" at 17875.76,9610.7 h60
  text "VIEWED FROM:" at 18070.76,9520.7 h50
  text "COMPONENT SIDE" at 18885.76,9520.7 h45
  text "SOLDER SIDE" at 19940.76,9520.7 h45
  text "X" at 18780.76,9510.7 h60
  text "REFERENCE:" at 18160.76,9400.7 h50
  text "AS SHOWN" at 18880.76,9395.7 h45
  text "PATTERN MASTER LIST" at 19945.76,9395.7 h45
  text "X" at 20880.76,9395.7 h60
  text "NC_DRILL FILES" at 20980.76,9395.7 h45
  text "X" at 18780.76,9390.7 h60
  text "PTH MINIMUM COPPER THICKNESS:" at 18390.76,9280.7 h50
  text "20um" at 19950.76,9280.7 h50
  text "X" at 19845.76,9275.7 h60
  text "OTHER" at 20980.76,9275.7 h50
  text "NPTH:" at 18410.76,9160.7 h50
  text "TENTED" at 18880.76,9155.7 h45
  text "X" at 19845.76,9155.7 h60
  text "PADS REMOVED" at 19945.76,9155.7 h45
  text "REMOVE PADS" at 20980.76,9155.7 h45
  text "X" at 18780.76,9150.7 h60
  text "2nd DRILL" at 18880.76,9035.7 h45
  text "BOTH" at 19945.76,9035.7 h45
  text "AS SHOWN" at 20430.76,9035.7 h45
  text "NONE" at 20980.76,9035.7 h45
  text "BOARD FINISH:" at 17875.76,8920.7 h60
  text "X" at 18780.76,8915.7 h60
  text "ETCHING" at 18880.76,8915.7 h45
  text "REFER PATTERN MASTER LIST" at 19945.76,8915.7 h45
  text "LEGEND / SCREEN PRINT:" at 18675.76,8800.7 h50
  text "NONE" at 19945.76,8795.7 h45
  text "COMPONENT" at 20430.76,8795.7 h45
  text "SOLDER" at 20980.76,8795.7 h45
  text "X" at 20330.76,8790.7 h60
  text "X" at 20880.76,8790.7 h60
  text "COLOUR:" at 18290.76,8680.7 h50
  text "WHITE" at 18880.76,8675.7 h45
  text "YELLOW" at 19945.76,8675.7 h45
  text "OTHER" at 20980.76,8675.7 h45
  text "X" at 18780.76,8670.7 h60
  text "X" at 18780.76,8555.7 h60
  text "LIQUID PHOTOIMAGEABLE" at 18880.76,8555.7 h45
  text "SCREEN PRINT" at 20430.76,8555.7 h45
  text "MATTE" at 18880.76,8435.7 h45
  text "GLOSS" at 19380.76,8435.7 h45
  text "GREEN" at 19945.76,8435.7 h45
  text "BLUE" at 20430.76,8435.7 h45
  text "G/Y" at 20980.76,8435.7 h45
  text "OTHER" at 21430.76,8435.7 h45
  text "X" at 19275.76,8430.7 h60
  text "SOLDER MASK COLOUR:" at 17875.76,8320.7 h45
  text "BLACK" at 18880.76,8315.7 h45
  text "GREEN" at 19380.76,8315.7 h45
  text "YELLOW" at 19945.76,8315.7 h45
  text "BLUE" at 20430.76,8315.7 h45
  text "OTHER" at 20980.76,8315.7 h45
  text "X" at 18775.76,8310.7 h60
  text "TRACK FINISH:" at 17875.76,8200.7 h60
  text "SELECTIVE SOLDER (HASL)" at 18880.76,8195.7 h45
  text "REFLOW SOLDER" at 20430.76,8195.7 h45
  text "SELECTIVE GOLD" at 18880.76,8075.7 h45
  text "um  (AREA" at 19945.76,8075.7 h45
  text "sq. mm)" at 21040.76,8075.7 h45
  text "X" at 18775.56,7956.14 h60
  text "IMMERSION GOLD" at 18880.76,7955.7 h45
  text "OTHER" at 20430.76,7955.7 h45
  text "EDGE BOARD" at 17875.76,7840.7 h60
  text "1.3um HARD GOLD OVER 5um     NICKEL / TIN-NICKEL" at 18880.76,7835.7 h45
  text "CONTACTS:" at 17875.76,7755.7 h60
  text "HARD FINISH GOLDE PLATE" at 18880.76,7715.7 h45
  text "OTHER" at 20430.76,7715.7 h45
  text "AS SHOWN" at 18880.76,7595.7 h45
  text "REFER" at 20430.76,7595.7 h45
  text "PROFILING:" at 17875.76,7475.7 h60
  text "AS DIMENSIONED, MEASURED AND CUT FROM SPECIFIED DATUM." at 18880.76,7475.7 h45
  text "X" at 18780.76,7470.7 h60
  text "REFER PCB BLANK DWG No." at 18885.76,7360.7 h50
  text "USE PROFILE / ROUTE TAPE SUPPLIED (REFER PATTERN MASTER LIST)" at 18885.76,7240.7 h50
  text "SQUARE CUT" at 18885.76,7120.7 h50
  text "N.C. ROUTE" at 19585.76,7120.7 h50
  text "V. SCORE" at 20285.76,7120.7 h50
  text "BLANK" at 20985.76,7120.7 h50
  text "ACCEPTABILITY:" at 17875.76,7015.7 h60
  text "MATERIALS AND WORKMANSHIP FOR ALL PRINTED WIRING BOARDS TO MEET" at 18750.76,7010.7 h50
  text "OR EXCEED THE REQUIREMENTS OF:" at 18750.76,6900.7 h50
  text "IPC-6011/12 AND IPC-A-600E" at 18890.76,6795.7 h50
  text "1" at 20290.76,6795.7 h50
  text "2" at 20640.76,6795.7 h50
  text "X" at 20535.76,6790.7 h60
  text "X" at 18785.76,6785.7 h60
  text "3" at 20990.76,6710.7 h50
  text "UL CERTIFICATION" at 18890.76,6675.7 h50
  text "AUSTEL" at 20290.76,6675.7 h50
  text "X" at 18785.76,6670.7 h60
  text "ML-P-55110F GRP" at 18870.76,6555.7 h40
  text "A" at 19590.76,6555.7 h50
  text "B" at 19940.76,6555.7 h50
  text "AS2546" at 20290.76,6555.7 h50
  text "OTHER" at 20990.76,6555.7 h50
  text "ADDITIONAL" at 17875.76,6440.7 h60
  text "NONE" at 18890.76,6430.7 h50
  text "SAMPLE PLAN" at 19590.76,6430.7 h50
  text "MIL-P-55110E SERIAL Nos. PER ORDER" at 20290.76,6430.7 h50
  text "REQUIREMENTS:" at 17875.76,6345.7 h60
  text "NONE" at 18890.76,6310.7 h50
  text "X" at 19481.27,6304.56 h60
  text "QUALITY RELEASE REPORT" at 19584.85,6301.92 h50
  text "X" at 19482.02,6185.78 h60
  text "OTHER" at 19584.62,6183.5 h50
  text "MICROSECTION SAMPLE REQUIRED" at 19883.83,6183.5 h50
  text "NONE" at 19590.76,6070.7 h50
  text "REQUIRED" at 20290.76,6070.7 h50
  text "PER ORDER" at 21190.76,6070.7 h50
  text "ELECTRICAL TEST:" at 17875.76,6065.7 h60
  text "X" at 20185.76,6065.7 h60
  text "NONE" at 19590.76,5950.7 h50
  text "1 SIDE" at 20285.76,5950.7 h45
  text "2 SIDES" at 20725.76,5950.7 h45
  text "MIN. PITCH" at 21185.76,5950.7 h50
  text "0.5mm" at 21720.76,5950.7 h50
  text "SURFACE MOUNT:" at 17875.76,5945.7 h60
  text "X" at 20637.77,5942.71 h60
  text "NONE" at 19590.76,5830.7 h50
  text "FOIL" at 20290.76,5830.7 h50
  text "LEGEND" at 20740.76,5830.7 h50
  text "REFER" at 21185.76,5830.7 h50
  text "X" at 20634.81,5829.17 h60
  text "MANUFACTURER'S ID/LOGO:" at 17875.76,5825.7 h60
  text "ISO9001/AS3901" at 19740.76,5710.7 h50
  text "NONE" at 21185.76,5710.7 h50
  text "MANUFACTURER'S ACCREDITATION:" at 17875.76,5705.7 h60
  text "X" at 19635.76,5705.7 h60
  text "PER ORDER" at 19590.76,5590.7 h50
  text "REFER" at 20290.76,5590.7 h50
  text "PACKAGING AND HANDLING:" at 17875.76,5585.7 h60
  text "X" at 19485.76,5580.7 h60
Mechanical 16:
  drawing of 1883 lines, arcs and shapes, not listed
  text "1" at 7819.93,15024.68 h31.5
  text "2" at 9750.59,15024.68 h31.5
  text "3" at 11689.94,15024.68 h31.5
  text "4" at 13630.59,15024.68 h31.5
  text "5" at 15570.59,15024.68 h31.5
  text "6" at 17500.59,15024.68 h31.5
  text "7" at 19450.59,15024.68 h31.5
  text "8" at 21380.59,15024.68 h31.5
  text "A" at 6948.59,13686.68 h31.5
  text "A" at 22248.59,13686.68 h31.5
  text "B" at 6948.59,10906.68 h31.5
  text "B" at 22248.59,10906.68 h31.5
  text "C" at 6948.59,8126.68 h31.5
  text "C" at 22248.59,8126.68 h31.5
  text "D" at 6948.59,5366.68 h31.5
  text "D" at 22248.59,5366.68 h31.5
  text "ENGINEER:" at 17723.59,5359.68 h31.5
  text "TITLE:" at 19223.59,5359.68 h31.5
  text "PCB DESIGNER:" at 17723.59,5064.68 h31.5
  text "PART NO.:" at 19223.59,5059.68 h31.5
  text "REV:" at 21323.59,5059.68 h31.5
  text "DATE:" at 17723.59,4759.68 h31.5
  text "DWG NO:" at 19223.59,4759.68 h31.5
  text "SCALE:" at 21323.59,4759.68 h31.5
  text "Altium Limited" at 16423.59,4659.68 h31.5
  text ".PRINT_DATE" at 17773.59,4639.68 h31.5
  text "12a Rodborough Rd" at 16423.59,4559.68 h31.5
  text "Frenchs Forest" at 16423.59,4459.68 h31.5
  text "FILE NAME:" at 17723.59,4459.68 h31.5
  text "NSW 2086" at 16423.59,4359.68 h31.5
  text ".PCB_FILE_NAME_NO_PATH" at 17773.59,4339.68 h31.5
  text "1" at 7819.93,4124.68 h31.5
  text "2" at 9750.59,4124.68 h31.5
  text "3" at 11689.94,4124.68 h31.5
  text "4" at 13630.59,4124.68 h31.5
  text "5" at 15570.59,4124.68 h31.5
  text "6" at 17500.59,4124.68 h31.5
  text "7" at 19450.59,4124.68 h31.5
  text "8" at 21380.59,4124.68 h31.5
Drill Drawing:
  text ".Legend" at 9352.82,4391.98 h31.5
